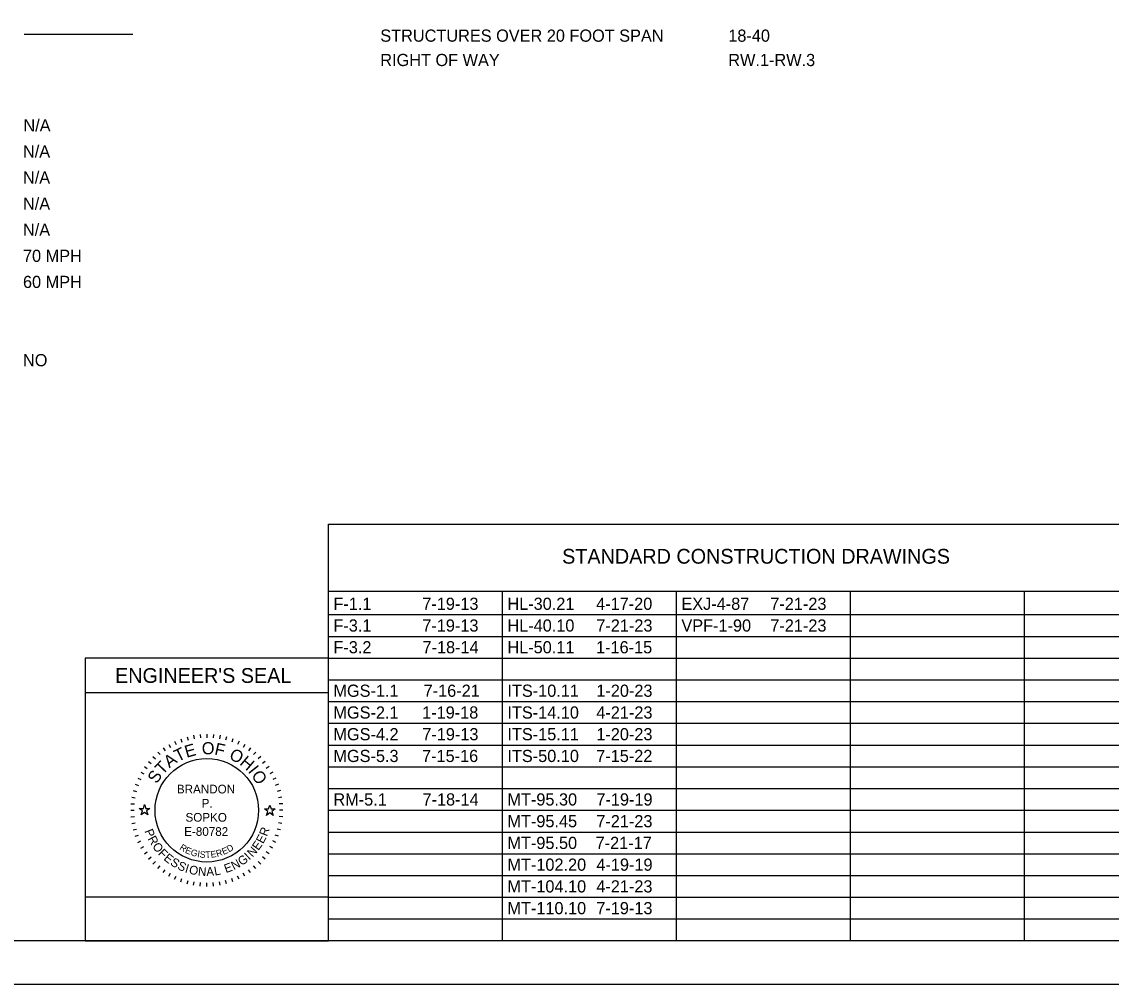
# Model space of a CAD drawing. Extents: x 0 to 34, y 0 to 22.
# Drawn here: x 7.72 to 20.25, y 0 to 11.07 of the extents above; entities that cross this region are included whole.
import ezdxf

# ---------------------------------------------------------------- set-up
doc = ezdxf.new("R2010")
doc.units = 0
for name, color, linetype in [('SH_Border', 7, 'Continuous'), ('SH_Cut_Line', 7, 'Continuous'), ('SH_Data', 7, 'Continuous'), ('SH_Text', 7, 'Continuous')]:
    doc.layers.add(name, color=color, linetype=linetype)

msp = doc.modelspace()

# ---------------------------------------------------------------- linework, layer by layer
at = {"layer": 'SH_Border'}
msp.add_lwpolyline([(1.5, 21.5), (33.5, 21.5), (33.5, 0.5), (1.5, 0.5)], close=True, dxfattribs=at)
at = {"layer": 'SH_Cut_Line'}
msp.add_lwpolyline([(0, 0), (34, 0), (34, 22), (0, 22)], close=True, dxfattribs=at)
at = {"layer": 'SH_Data'}
for p, q in [((9, 10.922), (7.75, 10.922)), ((11.25, 5.292), (24.7, 5.292)), ((11.25, 0.5), (11.25, 5.292)), ((11.25, 4.521), (24.7, 4.521)), ((13.25, 0.5), (13.25, 4.521)), ((15.25, 0.5), (15.25, 4.521)), ((17.25, 0.5), (17.25, 4.521)), ((19.25, 0.5), (19.25, 4.521)), ((11.25, 4.25), (24.7, 4.25)), ((11.25, 4), (24.7, 4)), ((11.25, 3.75), (8.45, 3.75)), ((8.45, 3.75), (8.45, 0.5)), ((11.25, 3.75), (24.7, 3.75)), ((11.25, 0.5), (11.25, 3.75)), ((11.25, 3.5), (24.7, 3.5)), ((11.25, 3.35), (8.45, 3.35)), ((11.25, 3.25), (24.7, 3.25)), ((11.25, 3), (24.7, 3)), ((9.413, 2.758), (9.433, 2.723)), ((9.48, 2.793), (9.497, 2.757)), ((9.551, 2.822), (9.564, 2.785)), ((9.624, 2.845), (9.634, 2.807)), ((9.698, 2.862), (9.705, 2.822)), ((9.774, 2.872), (9.777, 2.832)), ((9.85, 2.875), (9.85, 2.835)), ((9.926, 2.872), (9.923, 2.832)), ((10.002, 2.862), (9.995, 2.822)), ((10.076, 2.845), (10.066, 2.807)), ((10.149, 2.822), (10.136, 2.785)), ((10.22, 2.793), (10.203, 2.757)), ((10.287, 2.758), (10.267, 2.723)), ((9.288, 2.67), (9.313, 2.64)), ((9.348, 2.717), (9.371, 2.684)), ((10.352, 2.717), (10.329, 2.684)), ((10.412, 2.67), (10.387, 2.64)), ((11.25, 2.75), (24.7, 2.75)), ((9.18, 2.562), (9.21, 2.537)), ((9.231, 2.619), (9.26, 2.59)), ((10.469, 2.619), (10.44, 2.59)), ((10.52, 2.562), (10.49, 2.537)), ((9.092, 2.438), (9.127, 2.418)), ((9.133, 2.502), (9.166, 2.479)), ((10.567, 2.502), (10.534, 2.479)), ((10.608, 2.438), (10.573, 2.418)), ((11.25, 2.5), (24.7, 2.5)), ((9.028, 2.299), (9.065, 2.286)), ((9.057, 2.37), (9.093, 2.353)), ((10.643, 2.37), (10.607, 2.353)), ((10.672, 2.299), (10.635, 2.286)), ((8.988, 2.152), (9.028, 2.145)), ((9.005, 2.226), (9.043, 2.216)), ((10.695, 2.226), (10.657, 2.216)), ((10.712, 2.152), (10.672, 2.145)), ((11.25, 2.25), (24.7, 2.25)), ((8.978, 2.076), (9.018, 2.073)), ((10.722, 2.076), (10.682, 2.073)), ((8.975, 2), (9.015, 2)), ((8.978, 1.924), (9.018, 1.927)), ((10.722, 1.924), (10.682, 1.927)), ((10.725, 2), (10.685, 2)), ((11.25, 2), (24.7, 2)), ((8.988, 1.848), (9.028, 1.855)), ((9.005, 1.774), (9.043, 1.784)), ((10.695, 1.774), (10.657, 1.784)), ((10.712, 1.848), (10.672, 1.855)), ((9.028, 1.701), (9.065, 1.714)), ((9.057, 1.63), (9.093, 1.647)), ((10.643, 1.63), (10.607, 1.647)), ((10.672, 1.701), (10.635, 1.714)), ((11.25, 1.75), (24.7, 1.75)), ((9.092, 1.563), (9.127, 1.583)), ((9.133, 1.498), (9.166, 1.521)), ((10.567, 1.498), (10.534, 1.521)), ((10.608, 1.563), (10.573, 1.583)), ((9.18, 1.438), (9.21, 1.463)), ((9.231, 1.381), (9.26, 1.41)), ((10.469, 1.381), (10.44, 1.41)), ((10.52, 1.438), (10.49, 1.463)), ((11.25, 1.5), (24.7, 1.5)), ((9.288, 1.33), (9.313, 1.36)), ((9.348, 1.283), (9.371, 1.316)), ((9.413, 1.242), (9.433, 1.277)), ((10.287, 1.242), (10.267, 1.277)), ((10.352, 1.283), (10.329, 1.316)), ((10.412, 1.33), (10.387, 1.36)), ((9.48, 1.207), (9.497, 1.243)), ((9.551, 1.178), (9.564, 1.215)), ((9.624, 1.155), (9.634, 1.193)), ((9.698, 1.138), (9.705, 1.178)), ((9.774, 1.128), (9.777, 1.168)), ((9.85, 1.125), (9.85, 1.165)), ((9.926, 1.128), (9.923, 1.168)), ((10.002, 1.138), (9.995, 1.178)), ((10.076, 1.155), (10.066, 1.193)), ((10.149, 1.178), (10.136, 1.215)), ((10.22, 1.207), (10.203, 1.243)), ((11.25, 1.25), (24.7, 1.25)), ((11.25, 1), (24.7, 1)), ((11.25, 0.75), (24.7, 0.75)), ((11.25, 0.5), (8.45, 0.5))]:
    msp.add_line(p, q, dxfattribs=at)
for points in [[(9.074, 2.02), (9.121, 2.02), (9.135, 2.065), (9.149, 2.02), (9.196, 2.02), (9.158, 1.992), (9.173, 1.948), (9.135, 1.975), (9.097, 1.948), (9.112, 1.992)], [(10.513, 2.015), (10.56, 2.015), (10.574, 2.059), (10.589, 2.015), (10.635, 2.015), (10.598, 1.987), (10.612, 1.942), (10.574, 1.97), (10.536, 1.942), (10.551, 1.987)], [(11.25, 0.5), (11.25, 1), (8.45, 1), (8.45, 0.5)]]:
    msp.add_lwpolyline(points, close=True, dxfattribs=at)
msp.add_circle((9.85, 2), 0.595, dxfattribs=at)

# ---------------------------------------------------------------- texts
for s, height, p in [("ENGINEER'S SEAL", 0.17, (8.795, 3.465)), ('BRANDON', 0.1, (9.506, 2.194)), ('P.', 0.1, (9.79, 2.031)), ('SOPKO', 0.1, (9.605, 1.869)), ('E-80782', 0.1, (9.59, 1.706))]:
    msp.add_text(s, height=height, dxfattribs=at).set_placement(p)
for s, height, rotation, p in [('E', 0.14, 15.7571, (9.617, 2.603)), ('O', 0.14, 359.7812, (9.792, 2.644)), ('F', 0.14, 347.4362, (9.931, 2.642)), ('A', 0.14, 36.4747, (9.419, 2.482)), ('T', 0.14, 25.7167, (9.516, 2.554)), ('O', 0.14, 332.2586, (10.096, 2.598)), ('T', 0.14, 46.4344, (9.342, 2.4)), ('H', 0.14, 319.9136, (10.218, 2.532)), ('I', 0.14, 308.367, (10.317, 2.447)), ('S', 0.14, 57.1924, (9.276, 2.298)), ('O', 0.14, 303.1491, (10.356, 2.403)), ('P', 0.1, 291.494, (9.132, 1.762)), ('R', 0.1, 69.2322, (10.541, 1.694)), ('R', 0.1, 298.7311, (9.168, 1.673)), ('E', 0.1, 54.758, (10.443, 1.531)), ('E', 0.1, 61.9951, (10.497, 1.609)), ('O', 0.1, 306.4666, (9.218, 1.585)), ('F', 0.1, 314.7068, (9.284, 1.498)), ('E', 0.1, 321.4393, (9.347, 1.435)), ('R', 0.075, 327.8239, (9.53, 1.554)), ('E', 0.075, 337.7777, (9.594, 1.513)), ('G', 0.075, 344.2727, (9.658, 1.485)), ('I', 0.075, 350.6464, (9.737, 1.463)), ('S', 0.075, 353.7858, (9.765, 1.458)), ('T', 0.075, 3.0061, (9.835, 1.451)), ('E', 0.075, 8.9826, (9.899, 1.453)), ('R', 0.075, 17.6836, (9.969, 1.463)), ('E', 0.075, 23.3052, (10.041, 1.486)), ('D', 0.075, 31.466, (10.105, 1.514)), ('I', 0.1, 43.287, (10.338, 1.422)), ('N', 0.1, 47.0224, (10.374, 1.455)), ('S', 0.1, 328.6764, (9.422, 1.377)), ('S', 0.1, 335.9134, (9.504, 1.328)), ('I', 0.1, 343.1505, (9.592, 1.289)), ('E', 0.1, 20.0742, (10.07, 1.277)), ('N', 0.1, 27.3113, (10.16, 1.31)), ('G', 0.1, 35.0469, (10.25, 1.358)), ('O', 0.1, 346.8859, (9.638, 1.274)), ('N', 0.1, 355.1261, (9.745, 1.251)), ('A', 0.1, 2.8617, (9.846, 1.244)), ('L', 0.1, 10.0987, (9.942, 1.249))]:
    msp.add_text(s, height=height, rotation=rotation, dxfattribs=at).set_placement(p)
at = {"layer": 'SH_Text'}
for s, height, p in [('STRUCTURES OVER 20 FOOT SPAN', 0.14, (11.844, 10.838)), ('18-40', 0.14, (15.844, 10.838)), ('RIGHT OF WAY', 0.14, (11.844, 10.558)), ('RW.1-RW.3', 0.14, (15.844, 10.558)), ('N/A', 0.14, (7.742, 9.806)), ('N/A', 0.14, (7.737, 9.506)), ('N/A', 0.14, (7.737, 9.206)), ('N/A', 0.14, (7.737, 8.906)), ('N/A', 0.14, (7.737, 8.606)), ('70 MPH', 0.14, (7.737, 8.306)), ('60 MPH', 0.14, (7.737, 8.006)), ('NO', 0.14, (7.737, 7.106)), ('STANDARD CONSTRUCTION DRAWINGS', 0.17, (13.934, 4.836)), ('F-1.1', 0.14, (11.305, 4.305)), ('7-19-13', 0.14, (12.327, 4.305)), ('HL-30.21', 0.14, (13.305, 4.305)), ('4-17-20', 0.14, (14.325, 4.305)), ('EXJ-4-87', 0.14, (15.305, 4.305)), ('7-21-23', 0.14, (16.327, 4.305)), ('F-3.1', 0.14, (11.305, 4.055)), ('7-19-13', 0.14, (12.327, 4.055)), ('HL-40.10', 0.14, (13.305, 4.055)), ('7-21-23', 0.14, (14.327, 4.055)), ('VPF-1-90', 0.14, (15.305, 4.055)), ('7-21-23', 0.14, (16.327, 4.055)), ('F-3.2', 0.14, (11.305, 3.805)), ('7-18-14', 0.14, (12.329, 3.805)), ('HL-50.11', 0.14, (13.305, 3.805)), ('1-16-15', 0.14, (14.324, 3.805)), ('MGS-1.1', 0.14, (11.305, 3.305)), ('7-16-21', 0.14, (12.342, 3.305)), ('ITS-10.11', 0.14, (13.305, 3.305)), ('1-20-23', 0.14, (14.327, 3.305)), ('MGS-2.1', 0.14, (11.305, 3.055)), ('1-19-18', 0.14, (12.325, 3.055)), ('ITS-14.10', 0.14, (13.305, 3.055)), ('4-21-23', 0.14, (14.327, 3.055)), ('MGS-4.2', 0.14, (11.305, 2.805)), ('7-19-13', 0.14, (12.327, 2.805)), ('ITS-15.11', 0.14, (13.305, 2.805)), ('1-20-23', 0.14, (14.327, 2.805)), ('MGS-5.3', 0.14, (11.305, 2.555)), ('7-15-16', 0.14, (12.324, 2.555)), ('ITS-50.10', 0.14, (13.305, 2.555)), ('7-15-22', 0.14, (14.326, 2.555)), ('RM-5.1         ', 0.14, (11.305, 2.055)), ('7-18-14', 0.14, (12.329, 2.055)), ('MT-95.30', 0.14, (13.305, 2.055)), ('7-19-19', 0.14, (14.328, 2.055)), ('MT-95.45', 0.14, (13.305, 1.805)), ('7-21-23', 0.14, (14.327, 1.805)), ('MT-95.50', 0.14, (13.305, 1.555)), ('7-21-17', 0.14, (14.319, 1.555)), ('MT-102.20', 0.14, (13.305, 1.305)), ('4-19-19', 0.14, (14.328, 1.305)), ('MT-104.10', 0.14, (13.305, 1.055)), ('4-21-23', 0.14, (14.327, 1.055)), ('MT-110.10', 0.14, (13.305, 0.805)), ('7-19-13', 0.14, (14.327, 0.805))]:
    msp.add_text(s, height=height, dxfattribs=at).set_placement(p)

doc.saveas('drawing.dxf')
